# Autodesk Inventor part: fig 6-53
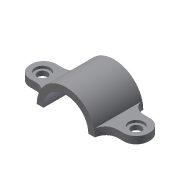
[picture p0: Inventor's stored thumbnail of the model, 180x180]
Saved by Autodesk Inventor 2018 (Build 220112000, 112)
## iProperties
Created: 2004-05
Part Number: fig 6-53
Document SubType Name: Modeling
Designer: CADCIM Technologies
Manufacturer: Standard
Standards Organization: Custom
Density: 1 g/cm^3
Material: Generic
Appearance: Default
Author: CADCIM Technologies
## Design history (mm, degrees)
node "Sketch1"
sketch "Sketch2"
  geometry: L1 (23.378, 0)-(17.996, 0); L2 (-17.996, 0)-(-23.378, 0); A1 r 23.378 centre (0, 0) between (23.378, 0) and (-23.378, 0); A2 r 17.996 centre (0, 0) between (17.996, 0) and (-17.996, 0)
  constraints: 4 end point, 4 point on circle, 2 centre point, 1 collinear, 1 horizontal
extrude "Extrusion1" new body sketch "Sketch2" stored distance "d0" = 38.75; taper "d1" = 0 deg
sketch "Sketch3"
  geometry: L1 (23.378, 0)-(17.996, 0); L2 (-17.996, 0)-(-23.378, 0) reference; L3 (-23.378, 0)-(-47.662, 0); L4 (-47.662, 0)-(-47.662, 5.722); L5 (-47.662, 5.722)-(-22.667, 5.722); A1 r 17.996 centre (0, 0) between (17.996, 0) and (-17.996, 0) reference; A2 r 23.378 centre (0, 0) between (23.378, 0) and (-23.378, 0) reference; 1 further point
  constraints: 10 end point, 5 point on circle, 2 centre point, 1 collinear, 1 horizontal, 1 midpoint, 1 parallel, 1 perpendicular, 3 other
extrude "Extrusion2" join sketch "Sketch3" stored distance "d2" = 21; taper "d3" = 0 deg
fillet "Fillet1" dims "d4" = 10
hole "Hole1" diameter "d7" = 8; stored, may be unused: countersink angle "d11" = 90 deg, drill point angle "d13" = 118 deg; dims "d5" = 10, "d6" = 10, "d8" = 6, "d9" = 12, "d10" = 2, "d12" = 12
fillet "Fillet2" dims "d14" = 9.5
mirror "Mirror1"
body "Solid1"
